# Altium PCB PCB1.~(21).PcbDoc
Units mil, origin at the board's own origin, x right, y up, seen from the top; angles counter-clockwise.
Board outline 944.8 x 947.11 mil, 2 copper layers (Top Layer, Bottom Layer); 41 components, 34 nets, 175 pads, 49 vias.
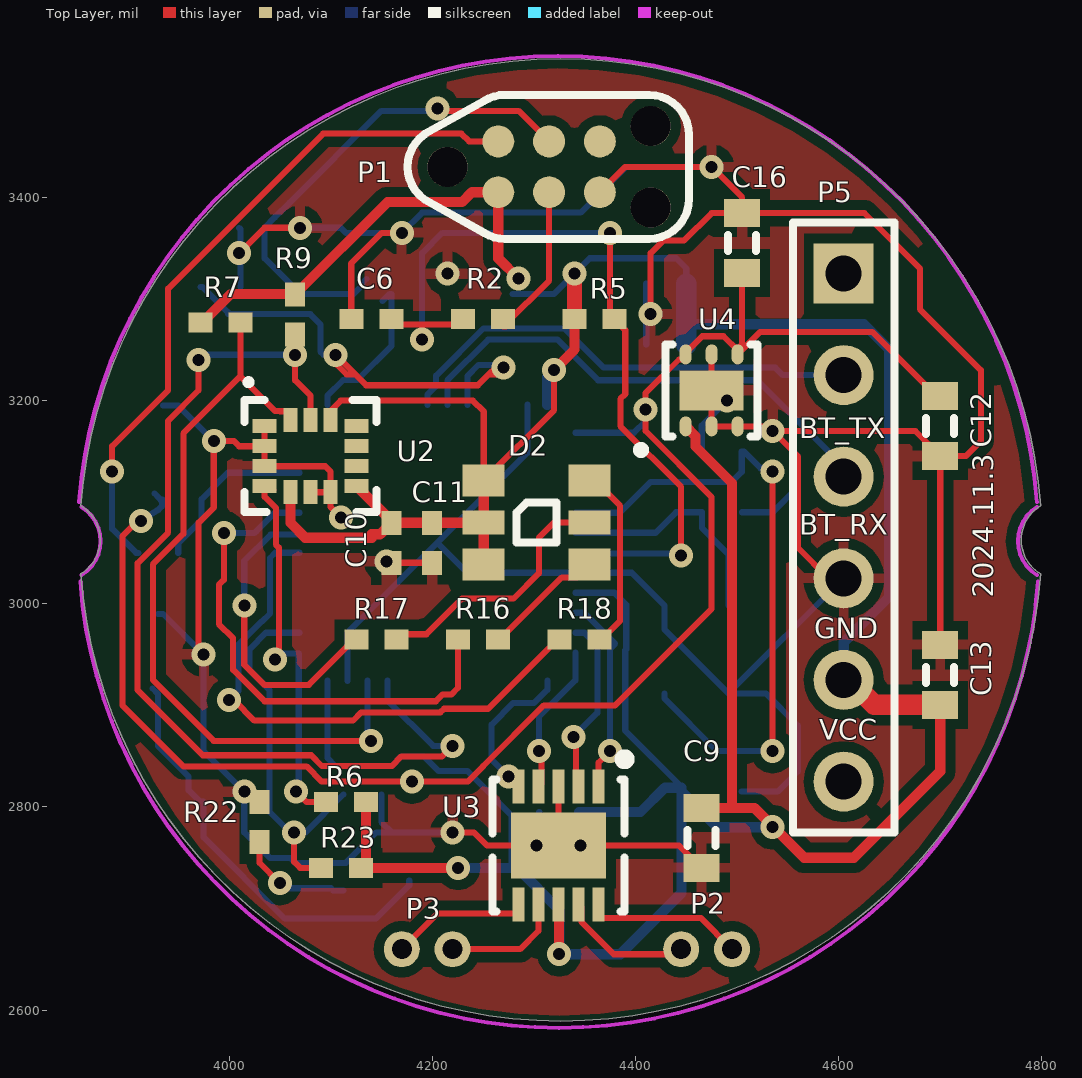
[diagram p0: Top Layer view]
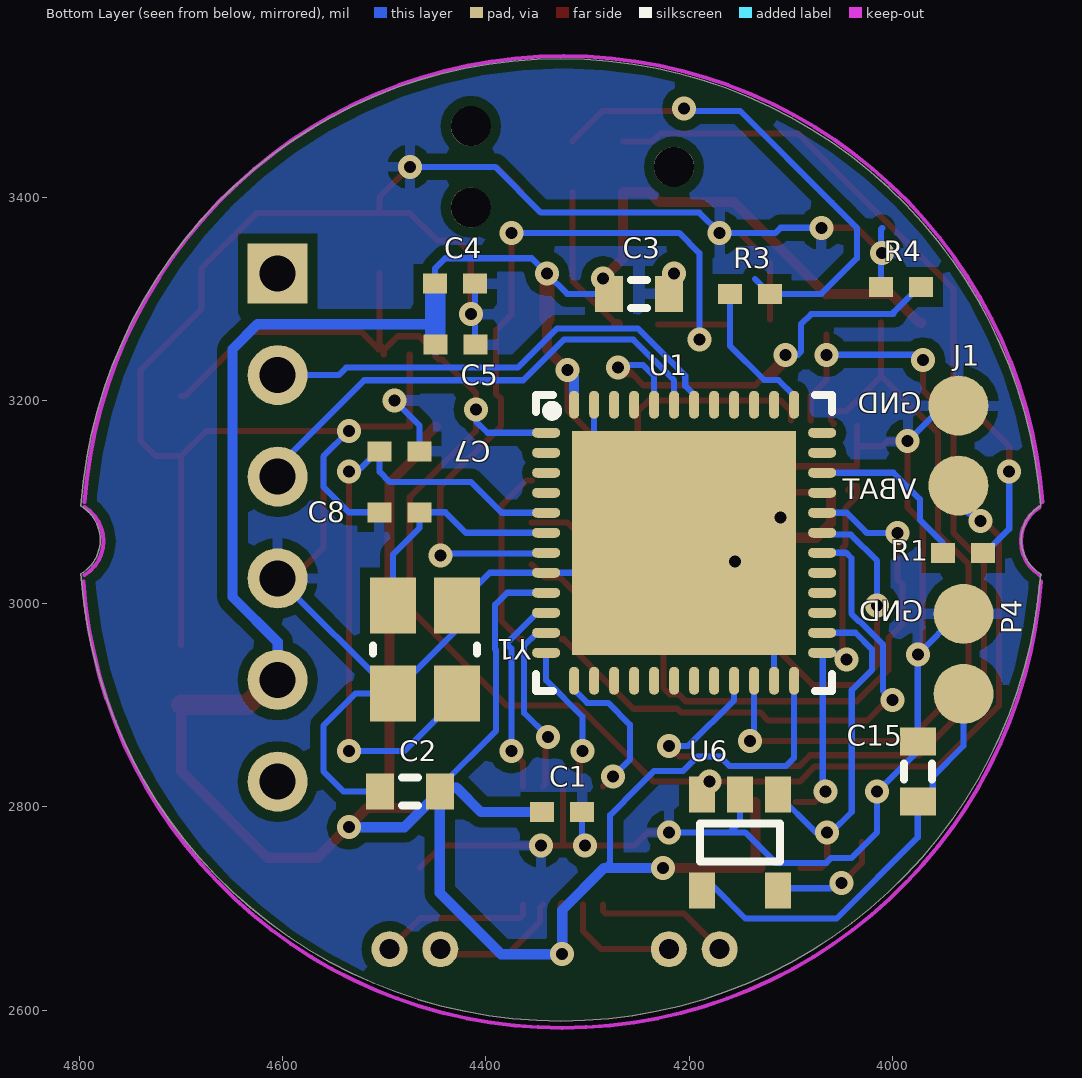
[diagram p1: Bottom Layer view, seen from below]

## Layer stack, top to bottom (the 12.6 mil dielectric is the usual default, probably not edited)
Top Solder: solder mask 0.4, Solder Resist, Dk 3.5
Top Layer: signal copper 1.4
Dielectric 1: dielectric 12.6, FR-4, Dk 4.8
Bottom Layer: signal copper 1.4
Bottom Solder: solder mask 0.4, Solder Resist, Dk 3.5

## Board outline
3854.06,3029.36 ccw(c3834.33,3062.83) 3854.08,3096.29 cw(c4326.46,3062.83) 4798.82,3096.36 4798.86,3096.31 ccw(c4818.58,3062.83) 4798.83,3029.37 cw(c4326.46,3062.83)

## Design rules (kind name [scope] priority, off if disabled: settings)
Clearance [All] p1: gap=10 except(5: Arc-Arc Track-SMDPad Arc-Track Arc-SMDPad Track-Track SMDPad-SMDPad)
PolygonConnect [All] p1: connectstyle=Relief reliefconductorwidth=10 reliefentries=4 polygonreliefangle="90 Angle" airgapwidth=10
RoutingVias [All] p1: holewidth=28 width=50 viastyle="Through Hole" minholewidth=28 minwidth=50 maxholewidth=28 maxwidth=50
SolderMaskExpansion [All] p1: expansion=4
UnpouredPolygon [All] p1: allowunpoured=FALSE
Width [All] p1: maxlimit=10 minlimit=5 preferedwidth=6 minimp=50.000000 maximp=50.000000 favimp=50.000000
29 further rules are at their usual default settings.

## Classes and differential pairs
net class RGBLED[1..3]: RGBLED1 RGBLED2 RGBLED3
net class MOTOR_CONTROL[1..4]: MOTOR_CONTROL1 MOTOR_CONTROL2 MOTOR_CONTROL3 MOTOR_CONTROL4

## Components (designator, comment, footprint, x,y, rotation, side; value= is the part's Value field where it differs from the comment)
C1 "10nF" 0402 4325,2795 r0 bottom
C2 "1uF" 0603 4475,2815 r180 bottom
C3 "4.7uF" 0603 4249.53,3305 r0 bottom
C4 "100nF" 0402 4430.31,3315 r0 bottom
C5 "100nF" 0402 4430,3255 r0 bottom
C6 "100nF" 0402 4140,3280 r0 top
C7 "22pF" 0402 4485,3150 r0 bottom
C8 "22pF" 0402 4485.31,3090 r180 bottom
C9 "10uF" 0603 4465,2769.53 r90 top
C10 "100nF" 0402 4160,3060 r90 top
C11 "100nF" 0402 4200,3060 r90 top
C12 "1uF" 0603 4700,3175 r90 top
C13 "1uF" 0603 4700,2930 r270 top
C15 "4.7uF" 0603 3975,2835 r270 bottom
C16 "4.7uF" 0603 4505,3355 r270 top
D2 "SMLVN6RGB1W1" "3.5x2.8 mm 6-SMD" 4302.83,3080 r0 top
J1 "78171-0002" "CHARGING PAD" 3935,3155.63 r90 bottom
P1 "TC2030-IDC-NL" TC2030-IDC-NL 4315,3430 r0 top
P2 "HEADER 2X1 0.05\" UNPOLARIZED" "HEADER 2X1 0.05\" - UNPOLARIZED" 4470,2660 r180 top
P3 "HEADER 2X1 0.05\" UNPOLARIZED" "HEADER 2X1 0.05\" - UNPOLARIZED" 4195,2660 r0 top
P4 "CHARGING PAD" "Charging Pad" 3930,2950.63 r90 bottom
P5 "Header 6" HDR1X6 4605,3325 r270 top
R1 "22R" 0402 3930.32,3050 r180 bottom
R2 "22R" 0402 4250,3280 r0 top
R3 "22R" 0402 4140.31,3305 r180 bottom
R4 "100K" 0402 3991.5,3311.84 r180 bottom
R5 "100K" 0402 4359.69,3280 r180 top
R6 "100K" 0402 4115,2805 r0 top
R7 "10K" 0402 3991.5,3276.84 r180 top
R9 "10K" 0402 4065,3284.68 r90 top
R16 "22.6R" 0402 4245,2965 r0 top
R17 "130R" 0402 4145,2965 r0 top
R18 "24.9R" 0402 4345,2965 r0 top
R22 "10K" 0402 4030,2785 r90 top
R23 "100K" 0402 4110,2740 r0 top
U1 "STM32F051C8U6" QFN50P700X700X60_HS-49L 4205,3060 r180 bottom
U2 "LSM6DS3" "LGA-14 2.5x3x0.86 mm 14L" 4080.28,3145.16 r0 top
U3 "A3901SEJTR-T" DFN50P300X300X75_HS-11N 4324.37,2761.93 r180 top
U4 "ADP122ACPZ-3.3-R7" "LFCSP-6 2.0X2.0X0.55" 4475,3210 r0 top
U6 "MCP73831T-2ACI/OT" SOT-23-OT5_L 4150,2765 r270 bottom
Y1 "7V-16.000MAAE-T" "3.2x2.5 CRYSTAL" 4460,2955 r90 bottom

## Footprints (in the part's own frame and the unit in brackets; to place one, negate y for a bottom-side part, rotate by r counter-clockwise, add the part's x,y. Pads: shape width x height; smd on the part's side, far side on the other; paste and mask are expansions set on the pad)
"3.2x2.5 CRYSTAL" [mm]
  rect 1.4x1.15 smd: 1(-1.1,-0.8) 2(1.1,-0.8) 3(1.1,0.8) 4(-1.1,0.8)
  silkscreen extent -0.1,-1.3 0.1,1.3, body extent -1.6,-1.25 1.6,1.25, height 0.8
"3.5x2.8 mm 6-SMD" [mm] "3.5 x 2.8 mm 6-SMD Flat Leads"
  rect 1.05x0.8 smd: 1(-1.325,1.05) 3(-1.325,-1.05) 4(1.325,-1.05) 6(1.325,1.05)
  rect 1.05x0.6 smd: 2(-1.325,0) 5(1.325,0)
  silkscreen extent -0.5,-0.5 0.5,0.5, body extent -1.75,-1.4 1.75,1.4, height 0.6
0402 [mm] "Chip Body 1.0 x 0.5 mm (LxW typ)"
  rect 0.6x0.5 smd: 1(-0.5,0) 2(0.5,0)
  body extent -0.55,-0.3 0.55,0.3, height 0.55
0603 [mm] "Chip Body 1.6 x 0.8 mm (LxW typ)"
  rect 0.7x0.9 smd: 1(-0.75,0) 2(0.75,0)
  silkscreen extent -0.2,-0.35 0.2,0.35, body extent -0.85,-0.48 0.85,0.48, height 0.9
"CHARGING PAD" [mm]
  round 1.5 smd paste-5: 1(-1,0) 2(1,0)
  body extent -1.75,-0.75 1.75,0.75, height 0
"Charging Pad" [mm]
  round 1.5 smd paste-5: 1(-1,0) 2(1,0)
  body extent -1.75,-0.75 1.75,0.75, height 0
DFN50P300X300X75_HS-11N [mm]
  rect 0.3x0.85 smd: 1(-1,-1.475) 2(-0.5,-1.475) 3(0,-1.475) 4(0.5,-1.475) 5(1,-1.475) 6(1,1.475) 7(0.5,1.475) 8(0,1.475) 9(-0.5,1.475) 10(-1,1.475)
  rect 2.38x1.65 smd: 11(0,0)
  silkscreen extent -1.78,-2.28 1.65,1.65, body extent -1.5,-1.5 1.5,1.5, height 0.75
HDR1X6 [mm] "Connector; Header; 6 Position"
  rect 1.5x1.5 hole 0.9: 1(0,0)
  round 1.5 hole 0.9: 2(2.54,0) 3(5.08,0) 4(7.62,0) 5(10.16,0) 6(12.7,0)
  silkscreen extent -1.27,-1.27 13.97,1.27
"HEADER 2X1 0.05\" - UNPOLARIZED" [mm]
  round 0.9 hole 0.5: 1(-0.635,0) 2(0.635,0)
  body extent -1.25,-0.6 1.25,0.6, height 0.01
"LFCSP-6 2.0X2.0X0.55" [mm] ". 6-Lead Lead Frame Chip Scale Package [LFCSP_UD]  2.00 mm?2.00 mm Body, Ultra Thin, Dual Lead  (CP-6-3)"
  oval 0.3x0.5 smd: 1(-0.65,-0.9) 2(0,-0.9) 3(0.65,-0.9) 4(0.65,0.9) 5(0,0.9) 6(-0.65,0.9)
  rect 1.6x1 smd: 7(0,0)
  silkscreen extent -1.86,-1.59 1.15,1.15, body extent -1,-1 1,1, height 0.6
"LGA-14 2.5x3x0.86 mm 14L" [mm] "LGA, 14-Leads, Body 3.00x2.50mm, Pitch 0.50mm, IPC High Density"
  rect 0.6x0.35 smd: 1(-1.15,0.75) 2(-1.15,0.25) 3(-1.15,-0.25) 4(-1.15,-0.75) 8(1.15,-0.75) 9(1.15,-0.25) 10(1.15,0.25) 11(1.15,0.75)
  rect 0.35x0.6 smd: 5(-0.5,-0.9) 6(0,-0.9) 7(0.5,-0.9) 12(0.5,0.9) 13(0,0.9) 14(-0.5,0.9)
  silkscreen extent -1.65,-1.4 1.65,1.9, body extent -1.5,-1.25 1.5,1.25, height 0.86
QFN50P700X700X60_HS-49L [mm] "QFN, 48-Leads, Body 7,00x7,00mm, Pitch 0,50mm, Thermal Pad 5,60x5,60mm, IPC High Density"
  oval 0.7x0.25 smd: 1(-3.45,2.75) 2(-3.45,2.25) 3(-3.45,1.75) 4(-3.45,1.25) 5(-3.45,0.75) 6(-3.45,0.25) 7(-3.45,-0.25) 8(-3.45,-0.75) 9(-3.45,-1.25) 10(-3.45,-1.75) 11(-3.45,-2.25) 12(-3.45,-2.75) 25(3.45,-2.75) 26(3.45,-2.25) 27(3.45,-1.75) 28(3.45,-1.25) 29(3.45,-0.75) 30(3.45,-0.25) 31(3.45,0.25) 32(3.45,0.75) 33(3.45,1.25) 34(3.45,1.75) 35(3.45,2.25) 36(3.45,2.75)
  oval 0.25x0.7 smd: 13(-2.75,-3.45) 14(-2.25,-3.45) 15(-1.75,-3.45) 16(-1.25,-3.45) 17(-0.75,-3.45) 18(-0.25,-3.45) 19(0.25,-3.45) 20(0.75,-3.45) 21(1.25,-3.45) 22(1.75,-3.45) 23(2.25,-3.45) 24(2.75,-3.45) 37(2.75,3.45) 38(2.25,3.45) 39(1.75,3.45) 40(1.25,3.45) 41(0.75,3.45) 42(0.25,3.45) 43(-0.25,3.45) 44(-0.75,3.45) 45(-1.25,3.45) 46(-1.75,3.45) 47(-2.25,3.45) 48(-2.75,3.45)
  rect 5.6x5.6 smd: 49(0,0)
  silkscreen extent -3.7,-3.7 3.7,3.7, body extent -3.55,-3.55 3.55,3.55, height 0.6
SOT-23-OT5_L [mm] "SOT23, 5-Leads, Body 2.9x1.6mm, Pitch 0.95mm, Lead Span 2.7mm, IPC High Density"
  rect 0.9x0.65 smd: 1(-1.2,0.95) 2(-1.2,0) 3(-1.2,-0.95) 4(1.2,-0.95) 5(1.2,0.95)
  silkscreen extent -0.48,-1 0.48,1, body extent -0.9,-1.55 0.9,1.55, height 1.45
TC2030-IDC-NL [mm] "TagConnector TC2030-IDC-NL"
  round 0.8 smd paste-1: 1(-1.27,-0.635) 2(-1.27,0.635) 3(0,-0.635) 4(0,0.635) 5(1.27,-0.635) 6(1.27,0.635)
  round 1 hole 1 unplated mask+0: ""(-2.54,0) ""(2.54,-1.016) ""(2.54,1.016)
  Top Layer pour cut-out: -1.27,-0.085 -1.27,0.085 -1.06,0.127 -0.881,0.246 -0.762,0.425 -0.72,0.635 -0.72,0.635 -0.55,0.635 -0.496,0.396 -0.343,0.205 -0.122,0.099 0.122,0.099 0.343,0.205 0.496,0.396 0.55,0.635 0.55,0.635 0.72,0.635 0.762,0.425 0.881,0.246 1.06,0.127 1.27,0.085 1.27,0.085 1.27,-0.085 1.06,-0.127 0.881,-0.246 0.762,-0.425 0.72,-0.635 0.72,-0.635 0.55,-0.635 0.496,-0.396 0.343,-0.205 0.122,-0.099 -0.122,-0.099 -0.343,-0.205 -0.496,-0.396 -0.55,-0.635 -0.55,-0.635 -0.72,-0.635 -0.762,-0.425 -0.881,-0.246 -1.06,-0.127 -1.27,-0.085
  silkscreen extent -3.54,-1.8 3.5,1.8, body extent -1.67,-1.03 1.67,1.03, height 0

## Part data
C1: "10nF 0402 X7R 25V ±5%"
C2 C12 C13: "1uF 0603 X5R 10V ±10%"
C3 C15 C16: "4.7uF 0603 X5R 10V ±10%"
C4 C5 C6 C10 C11: "100nF 0402 X7R 16V ±10%"
C7 C8: "22pF 0402 NP0/CG0 50V ±5%"
C9: "10uF 0603 X5R 6.3V ±20%"
D2: "ROHM SMLVN6RGB1W1 LED Tri-Color Blue/Green/Red Chip LED 6-Pin 1411 T/RLED Tri-Color Blue/Green/Red Chip LED 6-Pin 1411"
J1: "Molex Pico-EZmate? Wire-to-Board Header, 2 contacts"
P1: "TagConnect TC2030-IDC-NL SWD Programming Connector"
P5: "Header, 6-Pin"
R1 R2 R3: "22R 0402 1/16W ±1%"
R4 R5 R6 R23: "100K 0402 1/16W ±1%"
R7 R9 R22: "10K 0402 1/16W ±1%"
R16: "22.6R 0402 1/16W ±0.05R"
R17: "130R 0402 1/16W ±0.05R"
R18: "24.9R 0402 1/16W ±0.05R"
U1: "STMICROELECTRONICS  STM32F051C8U6  MCU 32BIT CORTEX-M0 48MHZ UFQFPN-48"
U2: "STMicroelectronics iNEMO inertial module:   3D accelerometer and 3D gyroscope"
U3: "ALLEGRO MICROSYSTEMS - A3901SEJTR-T - IC, MOTOR DRIVER"
U4: "Analog Devices ADP122ACPZ-3.3-R7 - 5.5 V Input, 300 mA, Low Quiescent  Current, CMOS Linear Regulator"
U6: "Miniature Single-Cell, Fully Integrated Li-Ion, Li-Polymer Charge Management Controller, 4.2V, 5-Pin SOT-23, Industrial Temperature, Tape and Reel"
Y1: "TXC - 7V-16.000MAAE-T, 16MHZ, 30PPM, 12PF - CRYSTAL"

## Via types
v1: diameter 23.62, hole 11.81, Top Layer to Bottom Layer, 49 vias

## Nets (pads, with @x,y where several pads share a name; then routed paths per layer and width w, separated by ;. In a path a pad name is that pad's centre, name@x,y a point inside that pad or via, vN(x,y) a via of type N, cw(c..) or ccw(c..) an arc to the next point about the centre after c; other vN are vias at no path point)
+3.3V: C1.2 C2.2 C3.2 C4.2 C5.2 C9.2 C10.2 C11.2 C13.2 D2.1 D2.2 D2.3 P1.1 P5.5 R5.2 R6.2 R7.2 R9.2 R23.2 U1.9 U1.24 U1.48 U2.5 U2.8 U2.12 U3.8 U4.1 | length 4431.6
  Top Layer w6: U2.12 4099.96,3189.96 4110,3200 4240,3200 4250.67,3189.33 D2.1 4319.96,3190.63 v1(4319.96,3230.04) ; U3.8 U3.8@4324.69,2703.54 ; v1@4324.69,2655.31 v1(4325,2655) ; P5.5 P5.5@4610.43,2925
  Top Layer w10: R7.2@3971.19,3276.21 R7.2 3973.79,3276.84 4001.94,3305 4064.37,3305 R9.2 4155.94,3395.31 4229.37,3395.31 4239.05,3405 P1.1 4265,3340 v1(4284.96,3320.04) ; U2.5 4060.59,3079.41 4075,3065 4140.51,3065 4140.51,3068.39 4148.7,3068.39 C10.2 C11.2 D2.2@4250.35,3079.69 ; U2.8 C10.2@4160,3081.18 ; R6.2 4134.69,2745 R23.2 v1(4225.59,2740.04) v1@4230.63,2735 ; D2.3 D2.2 D2.1 ; v1(4319.96,3230.04) 4340,3250.09 R5.2 ; v1@4324.69,2655.31 U3.8@4324.69,2703.54 ; U4.1 4459.09,3164.88 4459.09,3154.72 4495,3118.82 4495,2799.06 ; C9.2 4495,2799.06 ; C13.2 4700,2835 4615,2750 4566.03,2750 4516.97,2799.06 4495,2799.06
  Top Layer w15: R5.2 v1(4340,3325)
  Top Layer w20: P5.5@4610.43,2925 4634.96,2900.47 C13.2
  Bottom Layer w6: U1.24 4096.73,2848.27 4104.77,2840.23 4160.15,2840.23 4169.72,2849.81 4191.66,2849.81 4206.28,2835.19 4234.81,2835.19 4250.19,2819.81 4250.19,2819.72 4277.91,2792.01 4277.91,2745.68 4283.54,2740.04 ; C3.2 4320,3305 v1(4340,3325) 4355,3340 4440,3340 4450,3330 C4.2 ; U1.9 4379.21,3010.79 4391,2999 4391,2955.23 4390,2954.23 4390,2875.09 4445.47,2819.62 4445.47,2818.94 C2.2
  Bottom Layer w10: v1(4225.59,2740.04) 4283.54,2740.04 4325,2698.58 v1(4325,2655) 4385,2655 4445.47,2715.47 C2.2 4480.43,2780.04 v1(4534.96,2780.04) ; U1.48 4313.27,3223.27 v1@4315,3225 ; C1.2 4405,2795 4428.94,2818.94 C2.2@4445.47,2818.94 ; 4450,3275 4625,3275 4649.53,3250.47 4649.53,3006.56 4605,2962.03 P5.5
  Bottom Layer w20: C5.2@4450,3255 4450,3275 C4.2
BT_RX: P5.3 U1.43 | length 492.6
  Bottom Layer w6: U1.43 4214.84,3219.84 4255,3260 4323.33,3260 4363.33,3220 4520,3220 4605,3135 P5.3
BT_TX: P5.2 U1.42 | length 471.7
  Bottom Layer w6: U1.42 4195.16,3205.72 4203.84,3214.41 4203.84,3224.4 4250.44,3271 4330,3271 4368.65,3232.35 4537.65,3232.35 4545,3225 P5.2
CHARGING: R23.1 U1.26 U6.1 | length 378.3
  Top Layer w6: v1(4064.13,2775.04) 4064.13,2745.96 4070.09,2740 R23.1
  Bottom Layer w6: U1.26 4036.33,2971.42 4020.19,2955.28 4020.19,2934.72 4034.72,2920.19 4034.81,2920.19 4040,2915 4040,2795 4060,2775 4075.35,2775 U6.1
GND: C1.1 C2.1 C3.1 C4.1 C5.1 C6.1 C7.1 C8.1 C9.1 C10.1 C11.1 C12.1 C13.1 C15.1 C16.1 J1.2 P1.5 P4.2 P5.4 R4.1 R22.2 U1.8 U1.23 U1.47 U1.49 U2.1 U2.2 U2.3 U2.6 U2.7 U3.3 U3.11 U4.2 U4.3 U4.5 U4.7 U6.2 Y1.2 Y1.4 | length 4874.7
  Top Layer w6: v1(3975,2950) 3970.11,2954.9 3970.11,3079.76 3985,3094.66 v1(3985,3160) 4005,3160 4010,3155 U2.2 ; v1(4010,3345) 4035.04,3370.04 v1(4070,3370.04) ; U2.1 U2.2 ; U2.6 U2.7 ; v1(4110,3085) 4099.96,3095.04 U2.7 ; C6.1 4120.31,3335 4150.31,3365 v1(4170,3365) ; C10.1 C11.1 ; v1(4220,2775) 4240.98,2775 4254.06,2761.93 v1(4302.72,2761.93) U3.11 ; U3.3 U3.11 ; P1.5 4390,3430 v1(4475,3430) 4505,3400 C16.1 ; v1(4415,3285) 4415,3345 4427.31,3357.31 4447.69,3357.31 4474.9,3384.53 C16.1 ; C9.1 4443.07,2761.93 v1(4346.02,2761.93) U3.11 ; U4.5 U4.7 U4.2 U4.3 4530.43,3174.57 v1(4535,3170) ; P5.4 4590,3025 4560,3055 4560,3145 v1(4535,3170) ; C13.1 C12.1 ; U2.2 U2.3 4094.68,3135.32 4099.96,3130.04 U2.7 ; C16.1 4625.47,3384.53 4680,3330 4680,3290 4740,3230 4740,3160 4725.47,3145.47 C12.1 ; v1(4535,3170) 4675.47,3170 C12.1
  Bottom Layer w6: P4.2 3935,2990 v1(3975,2950) C15.1 3975,2855 v1(4015,2815) 4015,2775 4040.14,2749.86 4060.23,2749.86 4065.09,2745 4115,2745 4145,2775 4160,2775 ; J1.2 3950,3195 v1(3985,3160) ; 4010,3370 4011.19,3368.81 R4.1 ; v1(4070,3370.04) 4109.96,3370.04 4115,3365 v1(4170,3365) 4190,3385 4346.02,3385 4391.02,3430 v1(4475,3430) ; U1.23 4116.42,2971.42 U1.49 ; U6.2 4150,2785 4160,2775 ; v1(4220,2775) 4160,2775 ; U1.47 4293.58,3148.58 U1.49 ; v1(4302.72,2761.93) 4305.31,2764.53 C1.1 ; C5.1@4410.63,3255 C4.1 ; C7.1 4465.31,3175.31 v1(4490,3200) ; C2.1 4540,2815 4560,2835 4560,2880 4528.31,2911.69 Y1.4 ; C8.1 4535,3090 4560,3115 4560,3145 v1(4535,3170) ; P5.4 4604.8,3025 Y1.4 ; U1.49 4234.53,3030.47 U1.8 4396.34,3030.47 Y1.2 4428.5,2974.69 Y1.4
  other v1: 4155,3041.57 4215,3325
I2C.SCL: R9.1 U1.21 U2.13 | length 986.7
  Top Layer w6: v1(3969.96,3240.04) 3969.96,3209.96 3940,3180 3940,3070 3910,3040 3910,2915 3974.15,2850.85 4080.9,2850.85 4091.51,2840.23 4160.15,2840.23 4169.72,2849.81 4209.81,2849.81 v1(4220,2860) ; R9.1 4065,3220 4080.32,3204.68 U2.13 U2.13
  Bottom Layer w6: v1@3970.04,3245.04 v1(4064.96,3245.04) ; U1.21 4155.79,2905 4200.79,2860 v1(4220,2860)
I2C.SDA: R7.1 U1.22 U2.14 | length 759.2
  Top Layer w6: R7.1 4011.19,3223.81 ; U2.14@4057.5,3177.5 U2.14@4058.1,3176.9 ; U2.14 4060.59,3185.51 4056.7,3189.4 4050.3,3189.4 4050.12,3189.57 4045.43,3189.57 4011.19,3223.81 ; v1(4139.96,2865.04) 3985,2865 3925,2925 3925,3038.66 3955,3068.66 3955,3167.62 4011.19,3223.81
  Bottom Layer w6: U1.22 4136.1,2868.9 v1(4139.96,2865.04)
IMU_INT: R6.1 U1.25 U2.4 | length 382.5
  Top Layer w6: U2.4@4043.81,3111.74 4039.92,3115.63 U2.4 4035,3105.3 4046.04,3094.26 4046.04,3058.11 4049.05,3055.09 4049.05,2953.96 v1@4045.48,2950.38 ; v1(4066.06,2815.03) 4076.1,2805 R6.1
  Bottom Layer w6: v1(4045,2945) 4045,2949.91 4046.09,2951 4068.44,2951 4068.57,2951.13 4068.57,2817.55 v1(4066.06,2815.03)
MCU_X1_16MHZ: C7.2 U1.5 Y1.1 | length 647.3
  Top Layer w6: v1(4535,2855) v1(4535,3130)
  Bottom Layer w6: U1.5 4384.53,3089.53 4415,3120 4495,3120 4504.69,3129.69 C7.2 4506.65,3150 4523.28,3133.37 4531.63,3133.37 v1(4535,3130) ; Y1.1 4428.5,2906.77 4480.28,2855 v1(4535,2855)
MCU_X2_16MHZ: C8.2 U1.6 Y1.3 | length 235.6
  Bottom Layer w6: U1.6 4419.84,3069.84 4440,3090 C8.2 4465.63,3074.37 4491.5,3048.5 Y1.3
MOTOR_CONTROL1: U1.10 U3.1 | length 199.3
  Top Layer w6: U3.1 4363.74,2843.74 v1(4375,2855)
  Bottom Layer w6: U1.10 4349.69,2991.1 4380,2960.79 4375,2955.79 v1(4375,2855)
MOTOR_CONTROL2: U1.11 U3.2 | length 177.6
  Top Layer w6: v1(4338.93,2868.98) 4341.49,2866.42 4341.49,2822.56 U3.2
  Bottom Layer w6: v1(4338.93,2868.98) 4362.61,2892.69 4362.61,2958.5 4349.69,2971.42 U1.11
MOTOR_CONTROL3: U1.12 U3.4 | length 154.4
  Top Layer w6: U3.4 4307.59,2822.91 4307.59,2837.13 4307.71,2837.25 4307.71,2857.52 4305,2854.81 v1(4305,2855)
  Bottom Layer w6: v1(4305,2855) 4305,2888.77 4340.83,2924.6 U1.12
MOTOR_CONTROL4: U1.13 U3.5 | length 150
  Top Layer w6: v1(4275,2830) U3.5
  Bottom Layer w6: v1(4275,2830) 4258.37,2846.63 4258.37,2881.04 4279.72,2902.39 4300.35,2902.39 4313.27,2915.32 U1.13
NetC15_2: C15.2 P4.1 U6.4 | length 423.8
  Bottom Layer w6: P4.1@3924.68,2916.57 P4.1 3930,2860 3960.28,2829.72 3960.28,2816.25 3971.06,2805.47 C15.2 3975,2770 4055,2690 4144.57,2690 4177.4,2722.83 U6.4@4177.4,2727.76
NetD2_4: D2.4 R16.2 | length 120.8
  Top Layer w6: R16.2 4266.65,2965 4327.57,3025.91 4342.25,3025.91 D2.4
NetD2_5: D2.5 R17.2 | length 256.4
  Top Layer w6: R17.2@4164.69,2970 4194.28,2970 4229.28,3005 4280,3005 4305,3030 4305,3065 4320,3080 D2.5
NetD2_6: D2.6 R18.2 | length 181.1
  Top Layer w6: D2.6 4359.92,3121.34 4384.91,3096.35 4384.91,2983.25 4366.65,2965 R18.2
NetP1_2: P1.2 R1.2 | length 686
  Top Layer w6: v1(3885,3130) 3885,3155 3940,3210 3940,3310 4092.69,3462.69 4228.54,3462.69 4236.22,3455 P1.2
  Bottom Layer w6: v1(3885,3130) 3885,3073.66 3908.66,3050 R1.2
NetP1_3: P1.3 R2.2 | length 149.8
  Top Layer w6: R2.2@4271.97,3275 4315,3318.03 P1.3
  Top Layer w10: R2.2@4270,3275 R2.2@4271.97,3275
NetP1_4: P1.4 R3.2 | length 494.3
  Top Layer w6: v1(4205,3487.5) 4207.5,3485 4285,3485 P1.4
  Bottom Layer w6: 4135.31,3319.69 4129.44,3313.81 4129.44,3311.84 4122.6,3305 R3.2 4070,3305 4035,3340 4035,3370 4045.19,3380.19 4045.19,3380.32 4059.72,3394.86 4059.86,3394.86 4150,3485 4202.5,3485 v1(4205,3487.5)
NetP2_1: P2.1 U3.10 | length 155.4
  Top Layer w6: U3.10 4363.74,2693.62 4366.65,2690.72 4464.28,2690.72 P2.1
NetP2_2: P2.2 U3.9 | length 131.6
  Top Layer w6: U3.9 4346.96,2700.95 4346.96,2686.69 4378.65,2655 4440,2655 P2.2
NetP3_1: P3.1 U3.6 | length 136.7
  Top Layer w6: P3.1 4205,2695 4282.09,2695 4285,2697.91 U3.6
NetP3_2: P3.2 U3.7 | length 117.9
  Top Layer w6: P3.2 4286.49,2660 4304.61,2678.13 4304.61,2703.78 U3.7
NetR4_2: R4.2 U1.44 | length 482.8
  Top Layer w6: v1@4100.83,3245 4098.58,3242.74 4115.63,3225.69 4124.31,3225.69 ; v1(4105,3245) 4124.31,3225.69 ; 4124.31,3225.69 4135,3215 4245,3215 4255.69,3225.69 ; 4255.69,3225.69 4262.35,3232.35 v1(4270,3232.35) 4263.34,3225.69 4255.69,3225.69
  Bottom Layer w6: R4.2 3973.79,3311.84 3998.79,3286.84 ; 3998.79,3285 4080,3285 4090,3275 4090,3248.13 4093.13,3245 v1(4105,3245) ; U1.44 4234.53,3223.97 4245.56,3235 4267.35,3235 v1(4270,3232.35)
NetR22_1: R22.1 U6.5 | length 121.3
  Top Layer w6: R22.1 4030,2745 v1(4049.96,2725.04) v1@4055,2720
  Bottom Layer w6: v1(4049.96,2725.04) 4055,2720 4100.35,2720 4102.6,2717.76 U6.5
NRST: C6.2 R2.1 R5.1 U1.7 | length 809.5
  Top Layer w6: C6.2@4165,3275 4190,3275 ; v1(4190,3260) 4190,3275 ; R2.1@4230.63,3275 4190,3275 ; v1(4374.96,3365.04) 4374.96,3284.41 R5.1 4390,3269.37 4390,3206.34 4385.19,3201.52 4385.19,3174.81 4445,3115 v1(4445,3047.68)
  Bottom Layer w6: v1(4190,3260) 4190,3344.91 4189.96,3344.96 4210,3365 v1@4370,3365 ; U1.7 4350.72,3050.16 4351.46,3049.42 4443.25,3049.42 v1(4445,3047.68)
RGBLED1: R17.1 U1.31 | length 302.4
  Top Layer w6: v1(4015,2998.31) 4015,2939.91 4034.72,2920.19 4078.54,2920.19 4123.35,2965 R17.1
  Bottom Layer w6: v1(4015,2998.31) 4015,3042.1 4040.97,3068.07 U1.31@4067.4,3068.07
RGBLED2: R16.1 U1.32 | length 512.4
  Top Layer w6: v1(3994.92,3069.48) 3995,3069.4 3995,3023.64 3990,3018.64 3990,2980 4004,2966 4004,2935 4035,2904 4203.53,2904 4210,2910.47 4218.72,2910.47 4225.31,2917.07 R16.1
  Bottom Layer w6: v1(3994.92,3069.48) 4025.07,3069.48 4026.83,3071.24 4045.12,3089.53 U1.32
RGBLED3: R18.1 U1.30 | length 554.8
  Top Layer w6: v1(4000,2905) 4005,2905 4025,2885 4122,2885 4130,2893 4208.08,2893 4211.74,2896.65 4255,2896.65 4323.35,2965 R18.1
  Bottom Layer w6: v1(4000,2905) 4009.19,2914.19 4009.19,2959.83 4031.77,2982.42 4032.42,2982.42 4040.33,2990.33 4040.33,3045 4045.48,3050.16 U1.30
SWCLK: R3.1 U1.37 | length 155.3
  Bottom Layer w6: U1.37 4096.73,3204.69 4112.24,3220.19 4126.29,3220.19 4160,3253.9 R3.1 4158.03,3305 R3.1@4151.19,3298.16
SWDIO: R1.1 U1.34 | length 169.4
  Bottom Layer w6: R1.1 3950,3059.66 3972.94,3082.6 3972.94,3102.94 3998.9,3128.9 U1.34
VBAT: C12.2 C16.2 J1.1 U1.1 U4.4 U4.6 U6.3 | length 1675.1
  Top Layer w6: v1(3913.35,3081.65) 3910.17,3081.65 3895,3066.49 3895,2900 3955.15,2839.85 4076.34,2839.85 4091.19,2825 v1(4180,2825) 4235,2825 4250.19,2840.19 4250.19,2840.28 4309.91,2900 4380,2900 4475,2995 4475,3105 4410,3170 v1(4410,3191.25) 4410,3207.49 4442.89,3240.38 4446.73,3240.38 4449.41,3243.07 U4.6 4449.41,3246.9 4465.78,3263.28 4486.69,3263.28 4500.59,3249.37 U4.4 ; U4.4@4500.59,3250.94 4505,3255.35 C16.2 ; U4.4@4503.27,3250.48 4505.64,3250.48 4522.69,3267.53 4633.06,3267.53 4696.06,3204.53 C12.2
  Bottom Layer w6: v1(3913.35,3081.65) 3930.43,3092.44 3933.95,3095.96 3934.6,3102.7 3934.52,3100.22 J1.1@3926.74,3108.48 ; U1.1 4398.5,3168.27 4410,3179.77 v1(4410,3191.25)
pads on no net: P1. P1.6 P5.1 P5.6 U1.2 U1.3 U1.4 U1.14 U1.15 U1.16 U1.17 U1.18 U1.19 U1.20 U1.27 U1.28 U1.29 U1.33 U1.35 U1.36 U1.38 U1.39 U1.40 U1.41 U1.45 U1.46 U2.9 U2.10 U2.11

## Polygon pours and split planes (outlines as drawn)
GND on Bottom Layer "Bottom Layer-No Net" (solid, remove dead copper, pour order 20): 3815,3585 4995,3585 5005,3575 5000,3570 5000,2500 3810,2500 3815,2505 3815,3580
GND on Top Layer "Bottom Layer-No Net" (solid, remove dead copper, pour order 24): 3825,3540 4800,3540 4800,2560 4795,2555 3825,2555 3825,3535

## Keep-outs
Keep-Out Layer:
  lines w3.94: 3852.48,3100 cw(c4323.74,3066.63) 4795,3100 ; 3853.74,3021.63 ccw(c4325,3055) 4796.26,3021.63 ; 3855,3028.23 ccw(c3834.13,3061.62) 3855,3095 ; 4795,3028.23 cw(c4815.87,3061.62) 4795,3095

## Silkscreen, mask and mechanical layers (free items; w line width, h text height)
Top Overlay:
  text "BT_TX" at 4561,3162.67 h20
  text "BT_RX" at 4561,3067.67 h20
  text "2024.11.3" at 4752.33,3006 h20 r90
  text "GND" at 4576,2966 h20
  text "VCC" at 4581,2866 h20
Bottom Overlay:
  text "GND" at 3971,3187.67 h20
  text "VBAT" at 3976,3102.67 h20
  text "GND" at 3969.42,2982.67 h20
Mechanical 2:
  lines w10: 3854.06,3029.36 ccw(c3834.33,3062.83) 3854.08,3096.29 cw(c4326.46,3062.83) 4798.82,3096.36 ; 3854.09,3029.31 ccw(c4326.46,3062.83) 4798.83,3029.37 cw(c4818.58,3062.83) 4798.86,3096.31
Mechanical 10:
  lines w3.94: 3853.74,3098.37 cw(c4325,3065) 4796.26,3098.37 ; 3852.56,3029.27 ccw(c4323.82,3062.64) 4795.08,3029.27 ; 3852.56,3029.25 ccw(c3831.69,3062.64) 3852.56,3096.02 ; 3852.56,3029.25 ccw(c3831.69,3062.64) 3852.56,3096.02 ; 3852.56,3029.27 ccw(c4323.82,3062.64) 4795.08,3029.27 ; 3852.56,3096 cw(c4323.82,3062.64) 4795.08,3096 ; 3852.56,3096 cw(c4323.82,3062.64) 4795.08,3096 ; 3857.56,3029.25 ccw(c3836.69,3062.64) 3857.56,3096.02 ; 3857.56,3029.27 ccw(c4328.82,3062.64) 4800.08,3029.27 ; 3857.56,3029.27 ccw(c4328.82,3062.64) 4800.08,3029.27 ; 3857.56,3029.25 ccw(c3836.69,3062.64) 3857.56,3096.02 ; 3857.56,3096 cw(c4328.82,3062.64) 4800.08,3096 ; 3857.56,3096 cw(c4328.82,3062.64) 4800.08,3096 ; 4795.08,3029.25 cw(c4815.94,3062.64) 4795.08,3096.02 ; 4795.08,3029.25 cw(c4815.94,3062.64) 4795.08,3096.02 ; 4800.08,3029.25 cw(c4820.94,3062.64) 4800.08,3096.02 ; 4800.08,3029.25 cw(c4820.94,3062.64) 4800.08,3096.02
